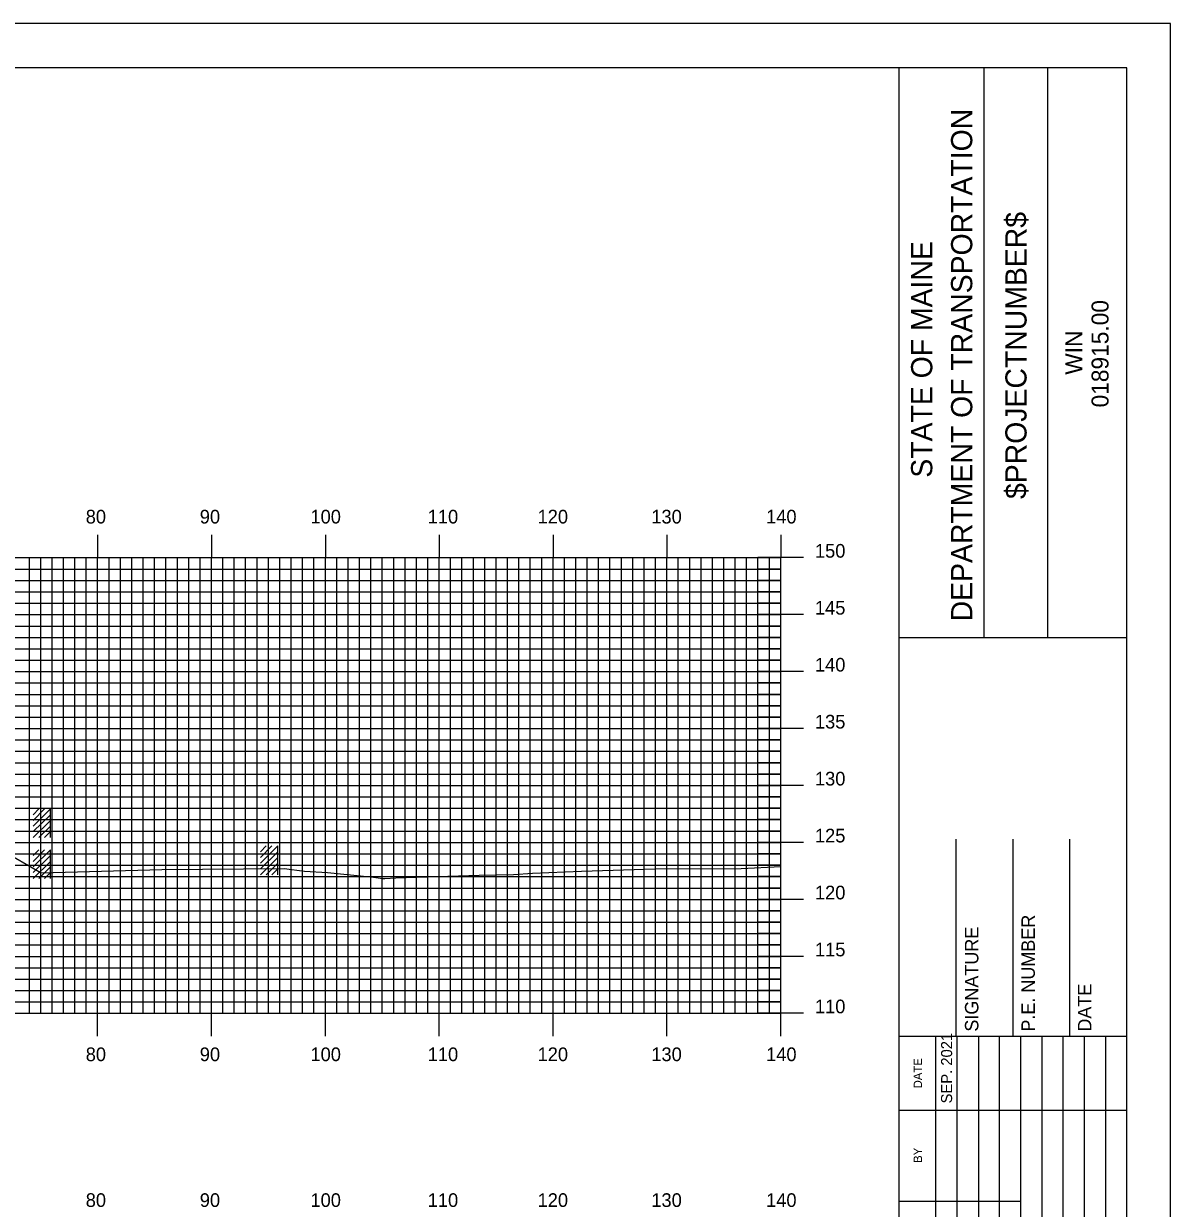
# Model space of a CAD drawing. Extents: x 1789730 to 1790074, y 442591 to 442811.
# Drawn here: x 1789969.7 to 1790070.4, y 442706.6 to 442810.5 of the extents above; entities that cross this region are included whole.
import ezdxf

# ---------------------------------------------------------------- set-up
doc = ezdxf.new("R2010")
doc.units = 0
for name, color, linetype in [('BORDER', 7, 'Continuous'), ('H_V ANNOTATION', 7, 'Continuous'), ('M_Buildings_Attachments', 7, 'Continuous'), ('M_Buildings_Rooftop', 7, 'Continuous'), ('MAJOR', 7, 'Continuous'), ('MINOR', 7, 'Continuous'), ('PLOT BOUNDARY', 7, 'Continuous'), ('S_Roadway_Centerline', 7, 'Continuous')]:
    doc.layers.add(name, color=color, linetype=linetype)

msp = doc.modelspace()

# ---------------------------------------------------------------- linework, layer by layer
at = {"layer": 'BORDER'}
for p, q in [((1790046.58, 442596.67), (1790046.58, 442806.67)), ((1790054.04, 442756.66), (1790054.04, 442806.66)), ((1790059.63, 442756.66), (1790059.63, 442806.66)), ((1790046.58, 442756.65), (1790066.58, 442756.65)), ((1790051.58, 442721.67), (1790051.58, 442738.97)), ((1790056.58, 442721.67), (1790056.58, 442738.97)), ((1790061.58, 442721.67), (1790061.58, 442738.97)), ((1790046.58, 442721.67), (1790066.58, 442721.67))]:
    msp.add_line(p, q, dxfattribs=at)
msp.add_lwpolyline([(1789746.58, 442596.67), (1790066.58, 442596.67), (1790066.58, 442806.67), (1789746.58, 442806.67)], close=True, dxfattribs=at)
for points in [[(1790049.81, 442715.17), (1790049.81, 442721.67)], [(1790051.68, 442686.68), (1790051.68, 442721.67)], [(1790053.54, 442721.67), (1790053.54, 442686.68)], [(1790055.4, 442686.68), (1790055.4, 442721.67)], [(1790057.27, 442686.68), (1790057.27, 442721.67)], [(1790059.13, 442686.68), (1790059.13, 442721.67)], [(1790060.99, 442686.68), (1790060.99, 442721.67)], [(1790062.86, 442686.68), (1790062.86, 442721.67)], [(1790064.72, 442686.68), (1790064.72, 442721.67)], [(1790049.81, 442686.68), (1790049.81, 442720.26)], [(1790046.58, 442715.17), (1790066.58, 442715.17)], [(1790046.58, 442707.17), (1790049.81, 442707.17)], [(1790049.81, 442707.17), (1790057.27, 442707.17)]]:
    msp.add_lwpolyline(points, dxfattribs=at)
at = {"layer": 'M_Buildings_Attachments'}
for p, q in [((1789970.53, 442736.52), (1789972.04, 442738.03)), ((1789970.53, 442737.01), (1789971.51, 442738.03)), ((1789970.53, 442737.51), (1789971.02, 442738.03)), ((1789972.04, 442735.5), (1789972.04, 442738.03)), ((1789970.53, 442736.03), (1789972.04, 442737.51)), ((1789970.53, 442735.5), (1789972.04, 442737.01)), ((1789971.02, 442735.5), (1789972.04, 442736.52)), ((1789971.51, 442735.5), (1789972.04, 442736.03))]:
    msp.add_line(p, q, dxfattribs=at)
at = {"layer": 'M_Buildings_Rooftop'}
for p, q in [((1789970.53, 442740.11), (1789972.04, 442741.62)), ((1789970.53, 442740.61), (1789971.51, 442741.62)), ((1789970.53, 442741.1), (1789971.02, 442741.62)), ((1789970.53, 442739.62), (1789972.04, 442741.1)), ((1789972.04, 442739.1), (1789972.04, 442741.62)), ((1789970.53, 442739.1), (1789972.04, 442740.61)), ((1789971.02, 442739.1), (1789972.04, 442740.11)), ((1789971.51, 442739.1), (1789972.04, 442739.62)), ((1789990.49, 442736.85), (1789992, 442738.36)), ((1789990.49, 442737.34), (1789991.48, 442738.36)), ((1789990.49, 442737.84), (1789990.99, 442738.36)), ((1789992, 442735.84), (1789992, 442738.36)), ((1789990.49, 442736.36), (1789992, 442737.84)), ((1789990.49, 442735.84), (1789992, 442737.34)), ((1789990.99, 442735.84), (1789992, 442736.85)), ((1789991.48, 442735.84), (1789992, 442736.36))]:
    msp.add_line(p, q, dxfattribs=at)
at = {"layer": 'MAJOR'}
for p, q in [((1789976.18, 442765.67), (1789976.18, 442763.67)), ((1789986.18, 442765.67), (1789986.18, 442763.67)), ((1789996.18, 442765.67), (1789996.18, 442763.67)), ((1790006.18, 442765.67), (1790006.18, 442763.67)), ((1790016.18, 442765.67), (1790016.18, 442763.67)), ((1790026.18, 442765.67), (1790026.18, 442763.67)), ((1790036.18, 442765.67), (1790036.18, 442763.67)), ((1789756.18, 442763.67), (1790036.18, 442763.67)), ((1789756.18, 442763.67), (1790036.18, 442763.67)), ((1789976.18, 442723.67), (1789976.18, 442763.67)), ((1789986.18, 442723.67), (1789986.18, 442763.67)), ((1789996.18, 442723.67), (1789996.18, 442763.67)), ((1790006.18, 442723.67), (1790006.18, 442763.67)), ((1790016.18, 442723.67), (1790016.18, 442763.67)), ((1790026.18, 442723.67), (1790026.18, 442763.67)), ((1790038.19, 442763.67), (1790034.18, 442763.67)), ((1790036.18, 442723.67), (1790036.18, 442763.67)), ((1790036.18, 442723.67), (1790036.18, 442763.67)), ((1789756.18, 442758.67), (1790036.18, 442758.67)), ((1790038.19, 442758.67), (1790034.18, 442758.67)), ((1789756.18, 442753.67), (1790036.18, 442753.67)), ((1790038.19, 442753.67), (1790034.18, 442753.67)), ((1789756.18, 442748.67), (1790036.18, 442748.67)), ((1790038.19, 442748.67), (1790034.18, 442748.67)), ((1789756.18, 442743.67), (1790036.18, 442743.67)), ((1790038.19, 442743.67), (1790034.18, 442743.67)), ((1789756.18, 442738.67), (1790036.18, 442738.67)), ((1790038.19, 442738.67), (1790034.18, 442738.67)), ((1789756.18, 442733.67), (1790036.18, 442733.67)), ((1790038.19, 442733.67), (1790034.18, 442733.67)), ((1789756.18, 442728.67), (1790036.18, 442728.67)), ((1790038.19, 442728.67), (1790034.18, 442728.67)), ((1789756.18, 442723.67), (1790036.18, 442723.67)), ((1789756.18, 442723.67), (1790036.18, 442723.67)), ((1789976.18, 442721.66), (1789976.18, 442723.67)), ((1789986.18, 442721.66), (1789986.18, 442723.67)), ((1789996.18, 442721.66), (1789996.18, 442723.67)), ((1790006.18, 442721.66), (1790006.18, 442723.67)), ((1790016.18, 442721.66), (1790016.18, 442723.67)), ((1790026.18, 442721.66), (1790026.18, 442723.67)), ((1790038.19, 442723.67), (1790034.18, 442723.67)), ((1790036.18, 442721.66), (1790036.18, 442723.67))]:
    msp.add_line(p, q, dxfattribs=at)
at = {"layer": 'MINOR'}
for p, q in [((1789970.18, 442723.67), (1789970.18, 442763.67)), ((1789971.18, 442723.67), (1789971.18, 442763.67)), ((1789972.18, 442723.67), (1789972.18, 442763.67)), ((1789973.18, 442723.67), (1789973.18, 442763.67)), ((1789974.18, 442723.67), (1789974.18, 442763.67)), ((1789975.18, 442723.67), (1789975.18, 442763.67)), ((1789977.18, 442723.67), (1789977.18, 442763.67)), ((1789978.18, 442723.67), (1789978.18, 442763.67)), ((1789979.18, 442723.67), (1789979.18, 442763.67)), ((1789980.18, 442723.67), (1789980.18, 442763.67)), ((1789981.18, 442723.67), (1789981.18, 442763.67)), ((1789982.18, 442723.67), (1789982.18, 442763.67)), ((1789983.18, 442723.67), (1789983.18, 442763.67)), ((1789984.18, 442723.67), (1789984.18, 442763.67)), ((1789985.18, 442723.67), (1789985.18, 442763.67)), ((1789987.18, 442723.67), (1789987.18, 442763.67)), ((1789988.18, 442723.67), (1789988.18, 442763.67)), ((1789989.18, 442723.67), (1789989.18, 442763.67)), ((1789990.18, 442723.67), (1789990.18, 442763.67)), ((1789991.18, 442723.67), (1789991.18, 442763.67)), ((1789992.18, 442723.67), (1789992.18, 442763.67)), ((1789993.18, 442723.67), (1789993.18, 442763.67)), ((1789994.18, 442723.67), (1789994.18, 442763.67)), ((1789995.18, 442723.67), (1789995.18, 442763.67)), ((1789997.18, 442723.67), (1789997.18, 442763.67)), ((1789998.18, 442723.67), (1789998.18, 442763.67)), ((1789999.18, 442723.67), (1789999.18, 442763.67)), ((1790000.18, 442723.67), (1790000.18, 442763.67)), ((1790001.18, 442723.67), (1790001.18, 442763.67)), ((1790002.18, 442723.67), (1790002.18, 442763.67)), ((1790003.18, 442723.67), (1790003.18, 442763.67)), ((1790004.18, 442723.67), (1790004.18, 442763.67)), ((1790005.18, 442723.67), (1790005.18, 442763.67)), ((1790007.18, 442723.67), (1790007.18, 442763.67)), ((1790008.18, 442723.67), (1790008.18, 442763.67)), ((1790009.18, 442723.67), (1790009.18, 442763.67)), ((1790010.18, 442723.67), (1790010.18, 442763.67)), ((1790011.18, 442723.67), (1790011.18, 442763.67)), ((1790012.18, 442723.67), (1790012.18, 442763.67)), ((1790013.18, 442723.67), (1790013.18, 442763.67)), ((1790014.18, 442723.67), (1790014.18, 442763.67)), ((1790015.18, 442723.67), (1790015.18, 442763.67)), ((1790017.18, 442723.67), (1790017.18, 442763.67)), ((1790018.18, 442723.67), (1790018.18, 442763.67)), ((1790019.18, 442723.67), (1790019.18, 442763.67)), ((1790020.18, 442723.67), (1790020.18, 442763.67)), ((1790021.18, 442723.67), (1790021.18, 442763.67)), ((1790022.18, 442723.67), (1790022.18, 442763.67)), ((1790023.18, 442723.67), (1790023.18, 442763.67)), ((1790024.18, 442723.67), (1790024.18, 442763.67)), ((1790025.18, 442723.67), (1790025.18, 442763.67)), ((1790027.18, 442723.67), (1790027.18, 442763.67)), ((1790028.18, 442723.67), (1790028.18, 442763.67)), ((1790029.18, 442723.67), (1790029.18, 442763.67)), ((1790030.18, 442723.67), (1790030.18, 442763.67)), ((1790031.18, 442723.67), (1790031.18, 442763.67)), ((1790032.18, 442723.67), (1790032.18, 442763.67)), ((1790033.18, 442723.67), (1790033.18, 442763.67)), ((1790034.18, 442723.67), (1790034.18, 442763.67)), ((1790035.18, 442723.67), (1790035.18, 442763.67)), ((1789756.18, 442762.67), (1790036.18, 442762.67)), ((1790036.18, 442762.67), (1790034.18, 442762.67)), ((1789756.18, 442761.67), (1790036.18, 442761.67)), ((1790036.18, 442761.67), (1790034.18, 442761.67)), ((1789756.18, 442760.67), (1790036.18, 442760.67)), ((1790036.18, 442760.67), (1790034.18, 442760.67)), ((1789756.18, 442759.67), (1790036.18, 442759.67)), ((1790036.18, 442759.67), (1790034.18, 442759.67)), ((1789756.18, 442757.67), (1790036.18, 442757.67)), ((1790036.18, 442757.67), (1790034.18, 442757.67)), ((1789756.18, 442756.67), (1790036.18, 442756.67)), ((1790036.18, 442756.67), (1790034.18, 442756.67)), ((1789756.18, 442755.67), (1790036.18, 442755.67)), ((1790036.18, 442755.67), (1790034.18, 442755.67)), ((1789756.18, 442754.67), (1790036.18, 442754.67)), ((1790036.18, 442754.67), (1790034.18, 442754.67)), ((1789756.18, 442752.67), (1790036.18, 442752.67)), ((1790036.18, 442752.67), (1790034.18, 442752.67)), ((1789756.18, 442751.67), (1790036.18, 442751.67)), ((1790036.18, 442751.67), (1790034.18, 442751.67)), ((1789756.18, 442750.67), (1790036.18, 442750.67)), ((1790036.18, 442750.67), (1790034.18, 442750.67)), ((1789756.18, 442749.67), (1790036.18, 442749.67)), ((1790036.18, 442749.67), (1790034.18, 442749.67)), ((1789756.18, 442747.67), (1790036.18, 442747.67)), ((1790036.18, 442747.67), (1790034.18, 442747.67)), ((1789756.18, 442746.67), (1790036.18, 442746.67)), ((1790036.18, 442746.67), (1790034.18, 442746.67)), ((1789756.18, 442745.67), (1790036.18, 442745.67)), ((1790036.18, 442745.67), (1790034.18, 442745.67)), ((1789756.18, 442744.67), (1790036.18, 442744.67)), ((1790036.18, 442744.67), (1790034.18, 442744.67)), ((1789756.18, 442742.67), (1790036.18, 442742.67)), ((1790036.18, 442742.67), (1790034.18, 442742.67)), ((1789756.18, 442741.67), (1790036.18, 442741.67)), ((1790036.18, 442741.67), (1790034.18, 442741.67)), ((1789756.18, 442740.67), (1790036.18, 442740.67)), ((1790036.18, 442740.67), (1790034.18, 442740.67)), ((1789756.18, 442739.67), (1790036.18, 442739.67)), ((1790036.18, 442739.67), (1790034.18, 442739.67)), ((1789756.18, 442737.67), (1790036.18, 442737.67)), ((1790036.18, 442737.67), (1790034.18, 442737.67)), ((1789756.18, 442736.67), (1790036.18, 442736.67)), ((1790036.18, 442736.67), (1790034.18, 442736.67)), ((1789756.18, 442735.67), (1790036.18, 442735.67)), ((1790036.18, 442735.67), (1790034.18, 442735.67)), ((1789756.18, 442734.67), (1790036.18, 442734.67)), ((1790036.18, 442734.67), (1790034.18, 442734.67)), ((1789756.18, 442732.67), (1790036.18, 442732.67)), ((1789756.18, 442731.67), (1790036.18, 442731.67)), ((1790036.18, 442732.67), (1790034.18, 442732.67)), ((1790036.18, 442731.67), (1790034.18, 442731.67)), ((1789756.18, 442730.67), (1790036.18, 442730.67)), ((1790036.18, 442730.67), (1790034.18, 442730.67)), ((1789756.18, 442729.67), (1790036.18, 442729.67)), ((1790036.18, 442729.67), (1790034.18, 442729.67)), ((1789756.18, 442727.67), (1790036.18, 442727.67)), ((1790036.18, 442727.67), (1790034.18, 442727.67)), ((1789756.18, 442726.67), (1790036.18, 442726.67)), ((1790036.18, 442726.67), (1790034.18, 442726.67)), ((1789756.18, 442725.67), (1790036.18, 442725.67)), ((1790036.18, 442725.67), (1790034.18, 442725.67)), ((1789756.18, 442724.67), (1790036.18, 442724.67)), ((1790036.18, 442724.67), (1790034.18, 442724.67))]:
    msp.add_line(p, q, dxfattribs=at)
at = {"layer": 'PLOT BOUNDARY'}
msp.add_lwpolyline([(1789730.4, 442590.55), (1790070.4, 442590.55), (1790070.4, 442810.55), (1789730.4, 442810.55)], close=True, dxfattribs=at)
at = {"layer": 'S_Roadway_Centerline'}
msp.add_lwpolyline([(1789967.67, 442738.05), (1789971.22, 442736.01), (1789981.81, 442736.3), (1789992.57, 442736.37), (1789994.34, 442736.16), (1789996.38, 442736.04), (1790000.4, 442735.61), (1790001.24, 442735.5), (1790001.39, 442735.51), (1790002.38, 442735.55), (1790009.68, 442735.79), (1790012.71, 442735.85), (1790014.37, 442735.96), (1790018.68, 442736.15), (1790025.14, 442736.34), (1790032.69, 442736.37), (1790036.18, 442736.55)], dxfattribs=at)

# ---------------------------------------------------------------- texts
at = {"layer": 'BORDER'}
for s, height, p in [('DEPARTMENT OF TRANSPORTATION', 1.8635, (1790053, 442758.08)), ('$PROJECTNUMBER$', 1.8635, (1790057.77, 442768.82)), ('STATE OF MAINE', 1.8635, (1790049.49, 442770.69)), ('018915.00', 1.491, (1790064.97, 442776.86)), ('WIN', 1.491, (1790062.66, 442779.73)), ('P.E. NUMBER', 1.1811, (1790058.5, 442722.06)), ('SIGNATURE', 1.181, (1790053.54, 442722.06)), ('DATE', 1.181, (1790063.46, 442722.06)), ('SEP. 2021', 0.969, (1790051.23, 442715.76)), ('DATE', 0.743, (1790048.59, 442717.08)), ('BY', 0.743, (1790048.59, 442710.54))]:
    msp.add_text(s, height=height, rotation=90, dxfattribs=at).set_placement(p)
at = {"layer": 'H_V ANNOTATION'}
for s, p in [('80', (1789975.13, 442766.67)), ('90', (1789985.15, 442766.67)), ('100', (1789994.87, 442766.67)), ('110', (1790005.17, 442766.67)), ('120', (1790014.82, 442766.67)), ('130', (1790024.81, 442766.67)), ('140', (1790034.89, 442766.67)), ('150', (1790039.18, 442763.67)), ('145', (1790039.18, 442758.67)), ('140', (1790039.18, 442753.67)), ('135', (1790039.18, 442748.67)), ('130', (1790039.18, 442743.67)), ('125', (1790039.18, 442738.67)), ('120', (1790039.18, 442733.67)), ('115', (1790039.18, 442728.67)), ('110', (1790039.18, 442723.67)), ('80', (1789975.13, 442719.47)), ('90', (1789985.15, 442719.47)), ('100', (1789994.87, 442719.47)), ('110', (1790005.17, 442719.47)), ('120', (1790014.82, 442719.47)), ('130', (1790024.81, 442719.47)), ('140', (1790034.89, 442719.47)), ('80', (1789975.13, 442706.67)), ('90', (1789985.15, 442706.67)), ('100', (1789994.87, 442706.67)), ('110', (1790005.17, 442706.67)), ('120', (1790014.82, 442706.67)), ('130', (1790024.81, 442706.67)), ('140', (1790034.89, 442706.67))]:
    msp.add_text(s, height=1.2, dxfattribs=at).set_placement(p)

doc.saveas('drawing.dxf')
